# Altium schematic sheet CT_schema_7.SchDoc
size 278 x 170 mm
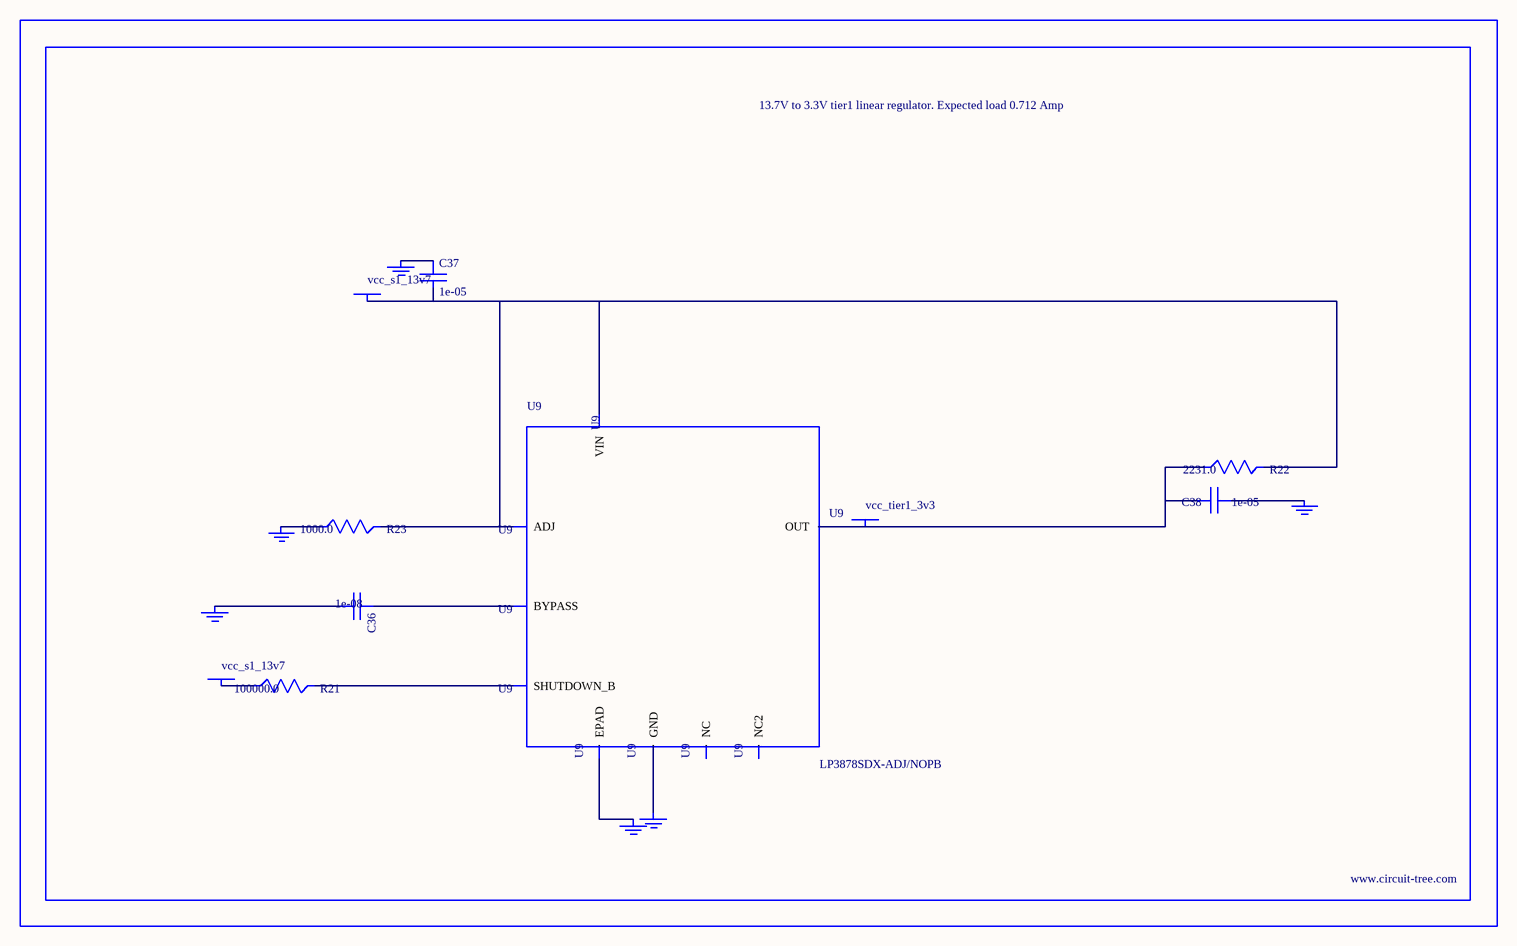
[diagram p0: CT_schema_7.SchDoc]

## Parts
BORDER6  (no value)
C36  1e-08  [C0402]
C37  1e-05  [C1210]
C38  1e-05  [C1210]
GND_INSTANCE_6_0  (no value)
GND_INSTANCE_6_1  (no value)
GND_INSTANCE_6_2  (no value)
GND_INSTANCE_6_3  (no value)
GND_INSTANCE_6_4  (no value)
GND_INSTANCE_6_5  (no value)
POWER_INSTANCE_6_0  vcc_s1_13v7
POWER_INSTANCE_6_1  vcc_s1_13v7
POWER_INSTANCE_6_2  vcc_tier1_3v3
R21  100000.0  [R0603]
R22  2231.0  [R0603]
R23  1000.0  [R0603]
U9  LP3878SDX-ADJ/NOPB  [WSON-8]

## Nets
NetC36_1: C36.1 U9.1(BYPASS)
NetC36_2: C36.2 GND_INSTANCE_6_0.0(GND)
NetC37_1: C37.1 GND_INSTANCE_6_1.0(GND)
NetC37_2: C37.2 POWER_INSTANCE_6_0.0(PWR) R22.2 R23.2 U9.4(VIN) U9.6(ADJ)
NetC38_1: C38.1 GND_INSTANCE_6_2.0(GND)
NetC38_2: C38.2 POWER_INSTANCE_6_2.0(PWR) R22.1 U9.5(OUT)
NetGND_INSTANCE_6_3_0: GND_INSTANCE_6_3.0(GND) R23.1
NetGND_INSTANCE_6_4_0: GND_INSTANCE_6_4.0(GND) U9.PAD(EPAD)
NetGND_INSTANCE_6_5_0: GND_INSTANCE_6_5.0(GND) U9.3(GND)
NetPOWER_INSTANCE_6_1_0: POWER_INSTANCE_6_1.0(PWR) R21.1
NetR21_2: R21.2 U9.8(SHUTDOWN_B)

Not connected (* = marked no-connect by the designer): U9 2(NC) 7(NC2)

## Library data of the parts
BORDER6 = BORDER_PAGE6
C36 = C0402C103K3RAC
C37 = C1210C106K5PACTU
C38 = GRM32DR61E106MA12L
GND_INSTANCE_6_0-GND_INSTANCE_6_5 = GND
POWER_INSTANCE_6_0-POWER_INSTANCE_6_2 = PWR
R21 = RC0603JR-07100KL
R22 = R22
R23 = RC0603JR-071KL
